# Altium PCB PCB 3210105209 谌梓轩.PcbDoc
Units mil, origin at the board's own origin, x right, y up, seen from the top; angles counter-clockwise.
Board outline 3937.01 x 1968.5 mil, 2 copper layers (Top Layer, Bottom Layer); 93 components, 82 nets, 314 pads, 119 vias.
Unrouted connection lines stored in the file: 3.
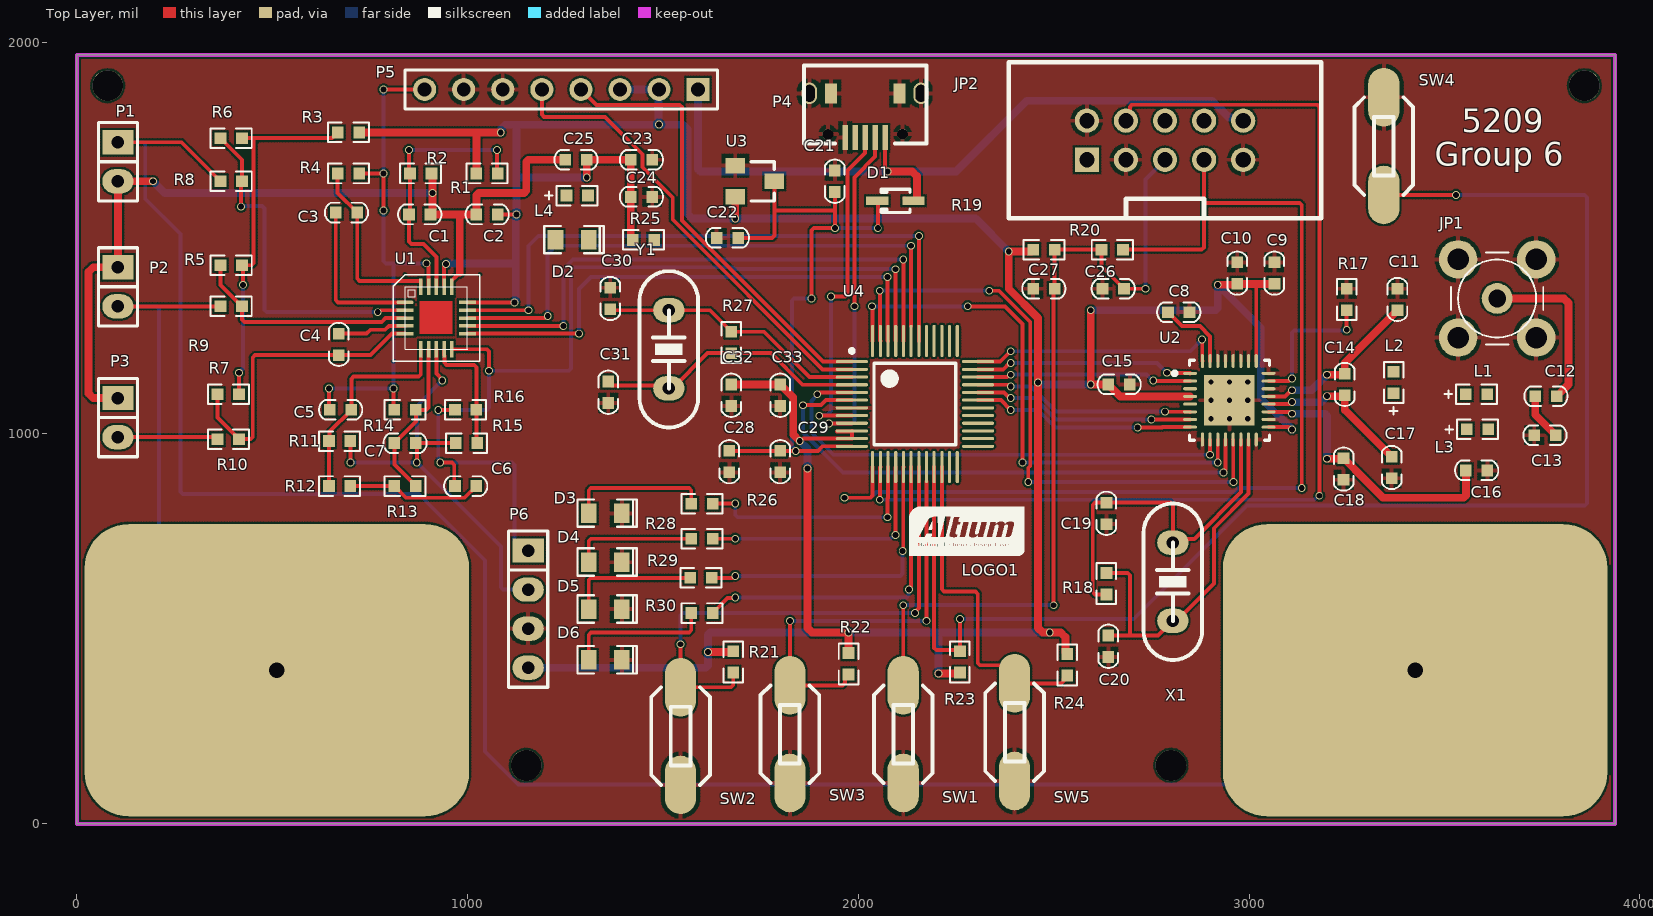
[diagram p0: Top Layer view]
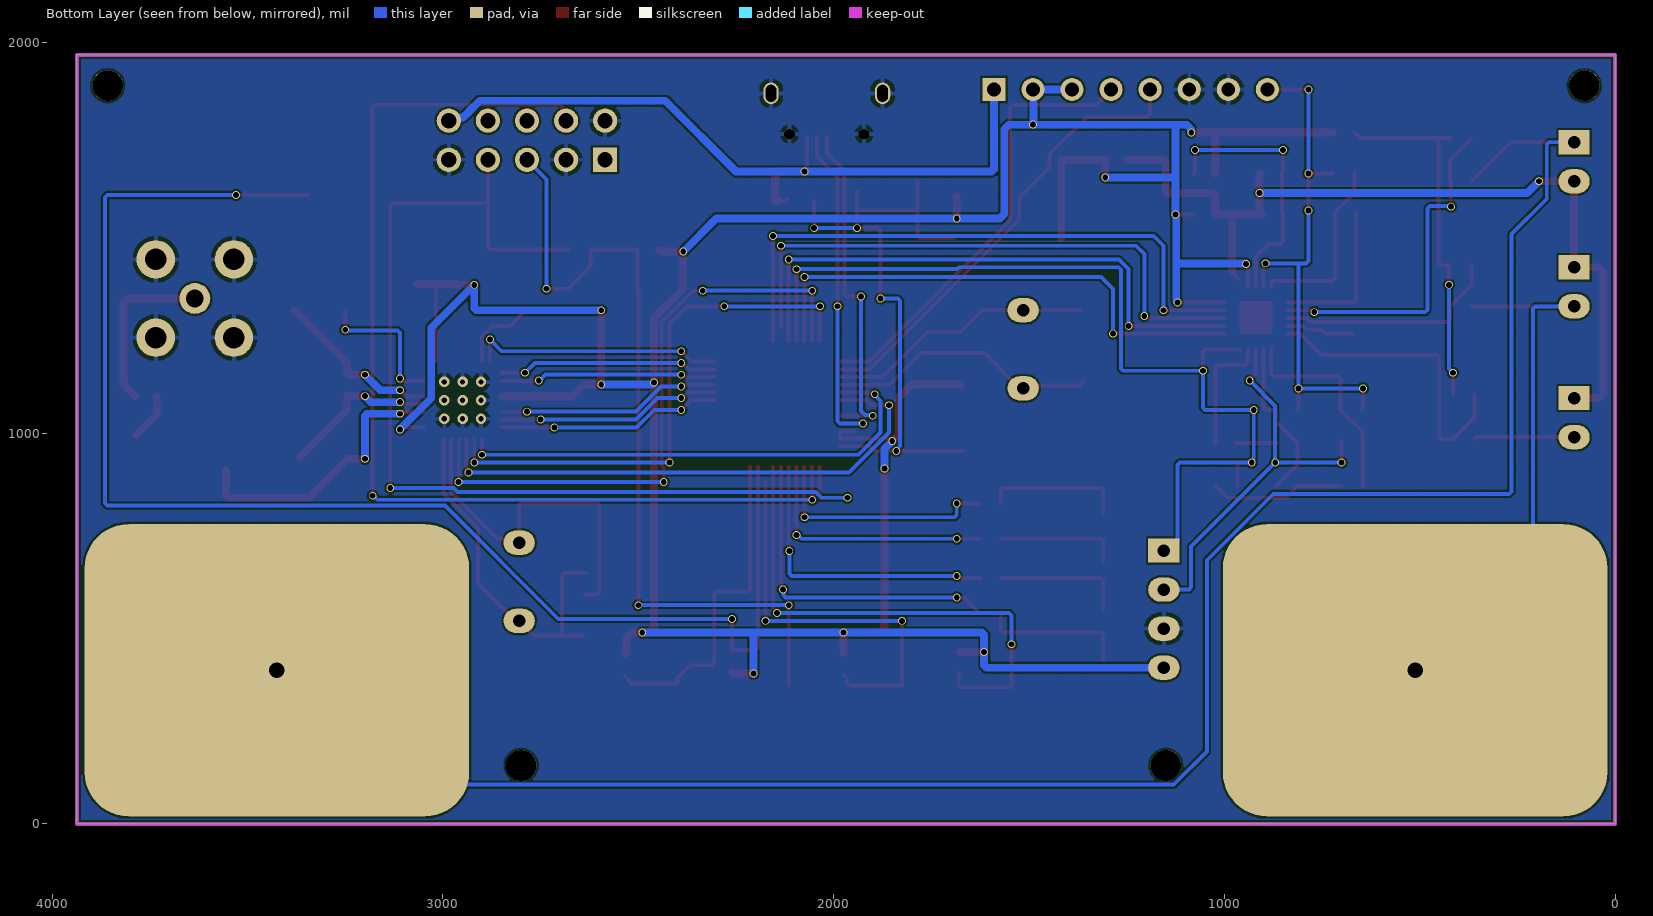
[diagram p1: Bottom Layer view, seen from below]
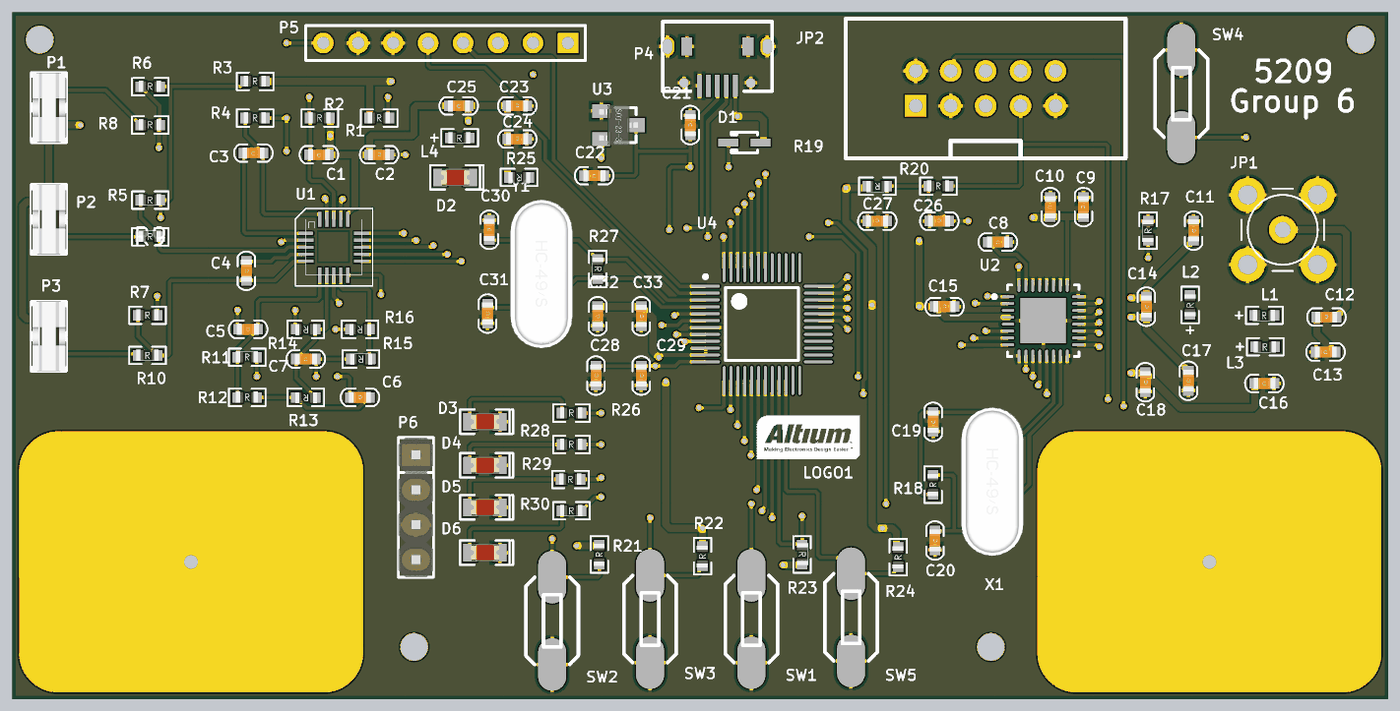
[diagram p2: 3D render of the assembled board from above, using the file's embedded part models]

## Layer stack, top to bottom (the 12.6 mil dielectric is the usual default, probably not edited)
Top Solder: solder mask 0.4, Solder Resist, Dk 3.5
Top Layer: signal copper 1.4
Dielectric 1: dielectric 12.6, FR-4, Dk 4.8
Bottom Layer: signal copper 1.4
Bottom Solder: solder mask 0.4, Solder Resist, Dk 3.5

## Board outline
0,0 0,1968.5 3937.01,1968.5 3937.01,0

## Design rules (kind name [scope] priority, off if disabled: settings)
Clearance [All] p1: gap=5 ignorepadtopadclearanceinfootprint=FALSE
PolygonConnect [All] p1: connectstyle=Relief reliefconductorwidth=10 reliefentries=4 polygonreliefangle="90 Angle" airgapwidth=10
RoutingVias [All] p1: holewidth=28 width=50 viastyle="Through Hole" minholewidth=28 minwidth=50 maxholewidth=28 maxwidth=50
SolderMaskExpansion [All] p1: expansion=4 istentingtop=FALSE
Width [All] p1: maxlimit=25 minlimit=10 preferedwidth=10
30 further rules are at their usual default settings.

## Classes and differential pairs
component class "Part3 3210105209 谌梓轩": C8 C9 C10 C11 C12 C13 C14 C15 C16 C17 C18 C19 C20 JP1 L1 L2 L3 R17 R18 U2 X1
component class "Part2 3210105209 谌梓轩": C21 C22 C23 C24 C25 C26 C27 C28 C29 C30 C31 C32 C33 D1 D2 D3 D4 D5 D6 JP2 L4 P4 P5 P6 R19 R20 R21 R22 R23 R24 R25 R26 R27 R28 R29 R30 SW1 SW2 SW3 SW4 SW5 U3 U4 Y1
component class "Part1 3210105209 谌梓轩": C1 C2 C3 C4 C5 C6 C7 LOGO1 P1 P2 P3 R1 R2 R3 R4 R5 R6 R7 R8 R9 R10 R11 R12 R13 R14 R15 R16 U1

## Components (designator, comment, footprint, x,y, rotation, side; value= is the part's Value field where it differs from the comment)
C1 "0.1uF" 0603C 877.5,1560 r0 top value=75nF
C2 "0.1uF" 0603C 1050,1560 r180 top value=75nF
C3 "0.22uF" 0603C 690,1565 r0 top value=75nF
C4 "1nF" 0603C 670,1227.5 r90 top value=75nF
C5 "0.22uF/NC" 0603C 675,1060 r180 top value=75nF
C6 "3.3nF/NC" 0603C 995,865 r180 top value=75nF
C7 "22nF/NC" 0603C 840,975 r0 top value=75nF
C8 "10nF" 0603C 2820,1310 r0 top value=75nF
C9 "33PF" 0603C 3065,1410 r270 top value=75nF
C10 "4.7nF" 0603C 2970,1410 r270 top value=75nF
C11 "18PF" 0603C 3380,1342.5 r90 top value=75nF
C12 "6.8PF" 0603C 3760,1095 r180 top value=75nF
C13 "NC" 0603C 3757.5,995 r0 top value=75nF
C14 "NC" 0603C 3245,1125 r90 top value=75nF
C15 "33P" 0603C 2667.5,1125 r180 top value=75nF
C16 "180PF" 0603C 3582.5,905 r0 top value=75nF
C17 "18PF" 0603C 3365,912.5 r90 top value=75nF
C18 "33nF" 0603C 3242.07,908.5 r90 top value=75nF
C19 "15P" 0603C 2635,795 r90 top value=75nF
C20 "15P" 0603C 2640,455 r90 top value=75nF
C21 "106" 0603C 1940,1645 r270 top value=75nF
C22 "104" 0603C 1665,1500 r0 top value=75nF
C23 "106" 0603C 1445,1700 r180 top value=75nF
C24 "104" 0603C 1445,1605 r180 top value=75nF
C25 "106" 0603C 1277.5,1700 r0 top value=75nF
C26 "106" 0603C 2652.5,1370 r180 top value=75nF
C27 "104" 0603C 2475,1370 r180 top value=75nF
C28 "104" 0603C 1670,927.5 r90 top value=75nF
C29 "106" 0603C 1800,927.5 r90 top value=75nF
C30 "30pF" 0603C 1365,1345 r270 top value=75nF
C31 "30pF" 0603C 1360,1105 r90 top value=75nF
C32 "104" 0603C 1675,1097.5 r90 top value=75nF
C33 "106" 0603C 1800,1097.5 r90 top value=75nF
D1 "1N5819" SOD-323 2095,1595 r180 top
D2 "LED2" LED0805R 1225,1495 r0 top
D3 "LED0805R" LED0805R 1310,795 r0 top
D4 "LED0805R" LED0805R 1310,670 r0 top
D5 "LED0805R" LED0805R 1310,550 r0 top
D6 "LED0805R" LED0805R 1310,420 r0 top
JP1 "BNC" SMA 3635,1345 r180 top
JP2 "JTAG" IDC10L 2585,1700 r0 top
L1 "39nH" 0603-D 3582.5,1100 r0 top
L2 "12nH" 0603-D 3370,1130 r90 top
L3 "39nH" 0603-D 3585,1010 r0 top
L4 "100MHz600R" 0603-D 1280.45,1608.5 r0 top
LOGO1 "LOGO" LOGO 2285,750 r0 top
P1 "LA" SIP2 105,1745 r270 top
P2 "LA" SIP2 105,1425 r270 top
P3 "LA" SIP2 105,1090 r270 top
P4 "USB-mini" USB-Micro 2017.6,1767.05 r0 top
P5 "Header 8" HDR1X8 1590,1880 r180 top
P6 "Header 4" SIP4 1155,550 r270 top
R1 "10M" 0603R 1050,1665 r0 top value=16K
R2 "10M" 0603R 880,1665 r0 top value=16K
R3 "0/NC" 0603R 695,1770 r0 top value=16K
R4 "10M" 0603R 695,1665 r0 top value=16K
R5 "10M" 0603R 395,1430 r0 top value=16K
R6 "10M" 0603R 395,1755 r0 top value=16K
R7 "NC/0" 0603R 387.5,1100 r0 top value=16K
R8 "180K" 0603R 395,1645 r0 top value=16K
R9 "180K" 0603R 395,1325 r0 top value=16K
R10 "360K/NC" 0603R 387.5,985 r0 top value=16K
R11 "100K/NC" 0603R 672.5,980 r0 top value=16K
R12 "1M/NC" 0603R 672.5,865 r0 top value=16K
R13 "1M/NC" 0603R 840,865 r180 top value=16K
R14 "NC/0" 0603R 840,1060 r180 top value=16K
R15 "100K/NC" 0603R 997.5,975 r180 top value=16K
R16 "1M/0" 0603R 995,1060 r180 top value=16K
R17 "22K" 0603R 3250,1342.5 r90 top value=16K
R18 "10M" 0603R 2635,615 r90 top value=16K
R19 "1K" 0603R 2475,1470 r180 top value=16K
R20 "10K" 0603R 2650,1470 r0 top value=16K
R21 "10K" 0603R 1680,415 r90 top value=16K
R22 "10K" 0603R 1975,410 r90 top value=16K
R23 "10K" 0603R 2260,415 r270 top value=16K
R24 "10K" 0603R 2535,407.5 r90 top value=16K
R25 "10M" 0603R 1450,1495 r180 top value=16K
R26 "3.6K" 0603R 1600,820 r0 top value=16K
R27 "10M" 0603R 1675,1232.5 r270 top value=16K
R28 "3.6K" 0603R 1600,730 r0 top value=16K
R29 "3.6K" 0603R 1597.5,630 r0 top value=16K
R30 "3.6K" 0603R 1600,540 r0 top value=16K
SW1 "SW-PB" SW-BP-SMD 2115,230 r90 top
SW2 "SW-PB" SW-BP-SMD 1545,225 r90 top
SW3 "SW-PB" SW-BP-SMD 1825,230 r90 top
SW4 "SW-PB" SW-BP-SMD 3345,1735 r270 top
SW5 "SW-PB" SW-BP-SMD 2400,235 r90 top
U1 "AD8232" QFN-20 840,1335 r0 top
U2 "NRF905" QFN32_M 2949.61,1084.53 r0 top
U3 "XC6206" SOT-23-123 1735,1645 r90 top
U4 "C8051F340/1/4/5" TQFP48_M 2145,1075 r0 top
X1 "16M" CY2 2805,720 r270 top
Y1 "3.2768MHz" CY2 1515,1315 r270 top

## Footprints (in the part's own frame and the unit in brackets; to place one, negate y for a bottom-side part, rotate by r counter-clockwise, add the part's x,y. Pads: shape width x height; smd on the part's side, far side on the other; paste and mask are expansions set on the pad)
0603-D [mil]
  rect 30x30 smd: A(-27.5,0) K(27.5,0)
  silkscreen extent -82,-25 52,25, body extent -33,-16 30,16, height 21
0603C [mil]
  rect 30x30 smd: 1(-27.5,0) 2(27.5,0)
  silkscreen extent -55,-25 55,25, body extent -31,-16 32,16, height 35
0603R [mil]
  rect 30x30 smd: 1(-27.5,0) 2(27.5,0)
  silkscreen extent -52,-25 52,25, body extent -32,-15 30,17, height 21
CY2 [mil]
  oval 62x80 hole 32: 1(0,0) 2(200,0)
  silkscreen extent -100,-75 300,75, body extent -116,-89 309,88, height 138
HDR1X8 [mm] "Connector; Header; 8 Position"
  rect 1.5x1.5 hole 0.9: 1(0,0)
  round 1.5 hole 0.9: 2(2.54,0) 3(5.08,0) 4(7.62,0) 5(10.16,0) 6(12.7,0) 7(15.24,0) 8(17.78,0)
  silkscreen extent -1.27,-1.27 19.05,1.27
IDC10L [mil]
  rect 62x62 hole 39: 1(0,0)
  round 62 hole 39: 2(0,100) 3(100,0) 4(100,100) 5(200,0) 6(200,100) 7(300,0) 8(300,100) 9(400,0) 10(400,100)
  silkscreen extent -200,-150 600,250
LED0805R [mil]
  rect 40x50 smd: 1(0,0) 2(85,0)
  silkscreen extent -29,-35 123,35, body extent 3,-24 83,25, height 43
LOGO [mil]
  silkscreen extent -154,-62 140,62
QFN32_M [mm] "QFN, 32-Leads, Body 5x5mm, Pitch 0.5mm, IPC Low Density"
  oval 0.9x0.2 smd: 1(-2.55,1.75) 2(-2.55,1.25) 3(-2.55,0.75) 4(-2.55,0.25) 5(-2.55,-0.25) 6(-2.55,-0.75) 7(-2.55,-1.25) 8(-2.55,-1.75) 17(2.55,-1.75) 18(2.55,-1.25) 19(2.55,-0.75) 20(2.55,-0.25) 21(2.55,0.25) 22(2.55,0.75) 23(2.55,1.25) 24(2.55,1.75)
  oval 0.2x0.9 smd: 9(-1.75,-2.55) 10(-1.25,-2.55) 11(-0.75,-2.55) 12(-0.25,-2.55) 13(0.25,-2.55) 14(0.75,-2.55) 15(1.25,-2.55) 16(1.75,-2.55) 25(1.75,2.55) 26(1.25,2.55) 27(0.75,2.55) 28(0.25,2.55) 29(-0.25,2.55) 30(-0.75,2.55) 31(-1.25,2.55) 32(-1.75,2.55)
  rect 3.3x3.3 smd: 33(0,0)
  silkscreen extent -3.67,-2.6 2.6,2.6, body extent -2.58,-2.58 2.58,2.58, height 0.8
QFN-20 [mm]
  oval 1.1x0.23 smd: 1(0,0)
  rect 1.1x0.23 smd: 2(0,-0.508) 3(0,-1.016) 4(0,-1.524) 5(0,-2.032) 11(4.064,-2.032) 12(4.064,-1.524) 13(4.064,-1.016) 14(4.064,-0.508) 15(4.064,0)
  rect 0.23x1.1 smd: 6(1.016,-3.048) 7(1.524,-3.048) 8(2.032,-3.048) 9(2.54,-3.048) 10(3.048,-3.048) 16(3.048,1.016) 17(2.54,1.016) 18(2.032,1.016) 19(1.524,1.016) 20(1.016,1.016)
  Top Layer region: 0.926,0.104 0.926,-2.046 3.076,-2.046 3.076,0.104
  Top Layer lines w0.025: -0.762,-3.841 -0.741,-3.821 ; -0.014,1.792 -0.014,1.812 ; 4.85,1.802 4.861,1.812
  silkscreen extent -0.76,-3.84 4.86,1.81
SIP2 [mil]
  rect 62x80 hole 32: 1(0,0)
  oval 62x80 hole 32: 2(100,0)
  silkscreen extent -50,-50 150,50, body extent -50,-50 150,50, height 646
SIP4 [mil]
  rect 62x80 hole 32: 1(-150,0)
  oval 62x80 hole 32: 2(-50,0) 3(50,0) 4(150,0)
  silkscreen extent -200,-50 200,50, body extent -200,-50 200,50, height 118
SMA [mm] "Connector; RF Coaxial, MCX, Thru-Hole; 5 Position; Right-Angle"
  round 2 hole 1.143: 1(0,0)
  round 2.5 hole 1.397: 2(-2.54,2.54) 2(-2.54,-2.54) 2(2.54,2.54) 2(2.54,-2.54)
  silkscreen extent -3,-3 3,3
SOD-323 [mm] "SOD-323/SC-76; 2 Leads; Body 1.7 x 1.3 mm, (LxW)"
  rect 1.45x0.55 smd: 1(1.175,0) 2(-1.175,0)
  silkscreen extent -0.95,-0.75 0.95,0.75
SOT-23-123 [mil]
  rect 40x50 smd: 1(40,50) 2(-40,50) 3(0,-50)
  silkscreen extent -50,-50 50,10, body extent -57,-55 57,55, height 47
SW-BP-SMD [mil]
  oval 150x80 smd: 1(-125,0) 2(125,0)
  silkscreen extent -125,-75 125,75
TQFP48_M [mm] "48-Pin Thin Quad Flat Pack 0.5 mm Pitch, IPC Low Density"
  oval 2.1x0.2 smd: 1(-4.1,2.75) 2(-4.1,2.25) 3(-4.1,1.75) 4(-4.1,1.25) 5(-4.1,0.75) 6(-4.1,0.25) 7(-4.1,-0.25) 8(-4.1,-0.75) 9(-4.1,-1.25) 10(-4.1,-1.75) 11(-4.1,-2.25) 12(-4.1,-2.75) 25(4.1,-2.75) 26(4.1,-2.25) 27(4.1,-1.75) 28(4.1,-1.25) 29(4.1,-0.75) 30(4.1,-0.25) 31(4.1,0.25) 32(4.1,0.75) 33(4.1,1.25) 34(4.1,1.75) 35(4.1,2.25) 36(4.1,2.75)
  oval 0.2x2.1 smd: 13(-2.75,-4.1) 14(-2.25,-4.1) 15(-1.75,-4.1) 16(-1.25,-4.1) 17(-0.75,-4.1) 18(-0.25,-4.1) 19(0.25,-4.1) 20(0.75,-4.1) 21(1.25,-4.1) 22(1.75,-4.1) 23(2.25,-4.1) 24(2.75,-4.1) 37(2.75,4.1) 38(2.25,4.1) 39(1.75,4.1) 40(1.25,4.1) 41(0.75,4.1) 42(0.25,4.1) 43(-0.25,4.1) 44(-0.75,4.1) 45(-1.25,4.1) 46(-1.75,4.1) 47(-2.25,4.1) 48(-2.75,4.1)
  silkscreen extent -4.22,-2.65 2.65,3.57, body extent -3.5,-3.5 3.5,3.5, height 1.6
USB-Micro [mm]
  oval 1x1.4 hole 0.7 slot 1.1 at 90 deg: 0(-3.625,2.615) 0(3.625,2.615)
  round 0.7 hole 0.7: 0(-2.425,-0.035) 0(2.425,-0.035)
  rect 0.8x1.3 smd: 0(-2.225,2.615) 0(2.225,2.615)
  rect 0.35x1.6 smd: 1(1.3,-0.254) 2(0.65,-0.254) 3(0,-0.254) 4(-0.65,-0.254) 5(-1.3,-0.254)
  silkscreen extent -3.98,-0.64 3.98,4.43

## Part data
C1 C2 C3 C4 C5 C6 C7 C8 C9 C10 C11 C12 C13 C14 C15 C16 C17 C18 C19 C20 C21 C22 C23 C24 C25 C26 C27 C28 C29 C30 C31 C32 C33: library part Cap, "Capacitor"
D1: library part DIODE
D2: "Typical RED, GREEN, YELLOW, AMBER GaAs LED"
D3 D4 D5 D6: library part LED0, "Typical INFRARED GaAs LED"
JP2: library part "Header 5X2", "Header, 5-Pin, Dual row"
L1 L2 L3 L4: library part INDUCTOR
P1 P2 P3: library part "Header 2", "Header, 2-Pin"
P5: "Header, 8-Pin"
P6: "Header, 4-Pin"
R1 R2 R3 R4 R5 R6 R7 R8 R9 R10 R11 R12 R13 R14 R15 R16 R17 R18 R19 R20 R21 R22 R23 R24 R25 R26 R27 R28 R29 R30: library part Res2, "Resistor"
U2: library part Component_1_1
X1 Y1: library part CRYSTAL

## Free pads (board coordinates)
  rrect30% 984.25x748.03 hole 39.37: 6(511.81,393.7) 7(3425.2,393.7)
  round 78.74 hole 78.74: 8(78.74,1889.76) 8(1150,150) 8(2800,150) 9(3858.27,1889.76)

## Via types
v1: diameter 20, hole 15, Top Layer to Bottom Layer, 110 vias
v2: diameter 25.98, hole 12.99, Top Layer to Bottom Layer, 9 vias

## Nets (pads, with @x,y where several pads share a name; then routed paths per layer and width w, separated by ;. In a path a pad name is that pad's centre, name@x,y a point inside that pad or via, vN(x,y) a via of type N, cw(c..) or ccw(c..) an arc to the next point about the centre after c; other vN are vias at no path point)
+3.3V: C2.1 C9.2 C10.2 C15.2 C23.2 C24.2 C25.2 C32.2 C33.2 P5.2 P5.3 P6.4 R1.1 R3.2 R19.2 R21.2 R22.2 R23.2 R24.2 R25.2 U1.15 U1.17 U2.4 U2.17 U2.25 U3.2 U4.10 U4.11 | length 9494.6
  Top Layer w10: U1.17 940,1425.58 945,1430.58 v1(945,1433.28) ; U1.15 v1(1120,1335) ; C2.1 v1(1125,1560) ; R25.2@1417.5,1500 R25.2 ; R21.2@1677.5,440 R21.2 ; v1(1850,980) 1852.71,980 1859.12,986.42 U4.11 U4.10 1982.52,1005.04 1945.12,1005.04 U4.10@1945.08,1005 ; C10.2@2967.5,1380 C10.2 ; 3017.5,1382.5 3018.5,1381.5 U2.25 ; U2.17 3101.66,1015.63 3107.29,1010 v1(3110,1010)
  Top Layer w20: R3.2 1022.66,1770 ; R1.1@1022.66,1665.16 1022.66,1770 ; v1(1085,1770) 1022.66,1770 ; v1(1305,1655) C25.2 C23.2 C24.2 R25.2@1417.5,1500 ; v1(1615,440) R21.2@1677.5,440 ; C32.2 C33.2 1833.28,1091.72 1833.28,996.72 v1(1850,980) ; v1(1685,1550) U3.2 ; v1(1870,910) 1870,501.72 1881.72,490 v1(1975,490) R22.2 ; v1(2205,385) 2257.5,385 R23.2 ; R19.2 2442.5,1465 v1(2385,1465) 2385,1370 2460,1295 v1(2460,1130) 2460,501.72 2471.72,490 2518.28,490 2530,478.28 2530,440 R24.2 ; v1(2595,1315) v1(2595,1125) C15.2 2670.63,1094.37 U2.4 ; v1(2920,1380) C10.2@2967.5,1380 ; C10.2 3017.5,1382.5 C9.2
  Bottom Layer w20: v1@945,1434.75 1123.28,1434.75 ; v1(1085,1770) 1085,1778.03 1096.72,1789.75 1125,1789.75 ; v1@1120,1336.46 1123.28,1339.75 1123.28,1434.75 ; 1125.42,1654.75 v1@1304.75,1654.75 ; P6.4 1609.14,400 1615,405.86 1615,484.14 1620.86,490 v1(1975,490) 2199.14,490 ; P5.3@1390.25,1879.75 P5.2@1489.75,1879.75 ; P5.2 1488.28,1878.28 1488.28,1791.72 v1(1490,1790) 1489.75,1789.75 1125,1789.75 ; v1@1490.25,1789.75 1551.57,1789.75 1563.28,1778.03 1563.28,1561.46 1575,1549.75 v1@1684.75,1549.75 ; v1(1685,1550) 2300,1550 v1(2385,1465) ; v1(1850,980) 1850.36,980 1870,960.36 v1(1870,910) ; v1(2205,385) 2205,484.14 2199.14,490 ; v1(2460,1130) 2465,1125 v1(2595,1125) ; v1(2490,490) 2199.14,490 ; v1(2595,1315) 2914.14,1315 2920,1320.86 v1(2920,1380) 3030,1270 3030,1090 v1(3110,1010) ; 1123.28,1434.75 1123.28,1558.28 v1(1125,1560) 1125,1789.75
+5V: D1.2 JP2.10 P4.1 P5.1 | length 1964.9
  Top Layer w10: P4.1 2068.78,1678.93 2075,1672.71 v1(2075,1670) ; D1.2@2117.72,1600.83 2123.54,1595 D1.2
  Top Layer w20: v1(2075,1670) 2138.28,1670 2150,1658.28 2150,1595.83 2149.17,1595 D1.2
  Bottom Layer w20: P5.1 1590,1675.86 1595.86,1670 v1(2075,1670) 2250,1670 2431,1851 2906.12,1851 2936,1821.12 2936,1820.7 2948.66,1808.04 2976.96,1808.04 JP2.10
AGND: C1.2 C2.2 C25.1 P1.2 P2.1 P3.1 R2.2 U1.16 | length 2325.9
  Top Layer w10: C1.2 970,1560 ; U1.16@960.47,1391.65 970,1401.18 980,1411.18
  Top Layer w20: P3.1 41.72,1090 30,1101.72 30,1413.28 41.72,1425 P2.1 P1.2 v1(195,1645) ; C1.2 915,1560 970,1560 C2.2 1022.5,1609.14 1028.36,1615 1144.14,1615 1150,1620.86 1150,1694.14 1155.86,1700 C25.1 ; R2.2 910,1662.5 v1(910,1615) C1.2@910,1565 ; 980,1411.18 980,1560
  Bottom Layer w20: v1(195,1645) 225,1615 v1(910,1615)
C2CK: JP2.7 R20.2 U4.13 | length 2737.5
  Top Layer w10: v1(1965,835) 2030.87,835 2036.73,840.86 U4.13 ; R20.2 2879.14,1470 2885,1475.86 2885,1589.67 ; JP2.7 2885,1589.67 ; v1(3135,860) 3135,1583.81 3129.14,1589.67 2885,1589.67
  Bottom Layer w10: v1(1965,835) 2031.72,835 2046.72,850 2963.28,850 2973.28,860 v1(3135,860)
C2D: JP2.4 U4.14 | length 2737.6
  Top Layer w10: v1(2055,830) 2055.71,830.71 2055.71,912.87 U4.14 ; JP2.4 2694.91,1809.91 2694.91,1835.14 2700.77,1841 3174.14,1841 3180,1835.14 v1(3180,840)
  Bottom Layer w10: v1(2055,830) 3167.29,830 3177.29,840 v1(3180,840)
D+: P4.3 U4.8 | length 876.2
  Top Layer w10: v1(1900,1045) 1900.24,1045.24 1983.35,1045.24 U4.8 ; v1(1930,1350) 1966.4,1350 1972.26,1355.86 1972.26,1672.26 2017.52,1717.52 2017.52,1756.97 P4.3
  Bottom Layer w10: v1(1900,1045) 1901.91,1046.91 1919.49,1046.91 1930,1057.43 v1(1930,1350)
D-: P4.2 U4.9 | length 875
  Top Layer w10: v1(1924.8,1025) 1925.19,1025.39 1983.19,1025.39 U4.9 ; v1(1990,1325) 1990,1655 2043.19,1708.19 P4.2
  Bottom Layer w10: v1(1924.8,1025) 1984.14,1025 1990,1030.86 v1(1990,1325)
GND: C8.2 C9.1 C10.1 C11.2 C13.1 C15.1 C16.2 C17.1 C18.1 C19.1 C20.1 C21.1 C22.1 C23.1 C24.1 C26.2 C27.2 C28.1 C29.1 C30.1 C31.1 C32.1 C33.1 D3.2 D4.2 D5.2 D6.2 JP1.2 JP2.2 JP2.3 JP2.9 P4.0 P4.5 P5.6 P5.7 P6.3 R17.2 SW1.1 SW2.1 SW3.1 SW4.1 SW5.1 U2.5 U2.9 U2.16 U2.18 U2.22 U2.24 U2.26 U2.27 U2.28 U2.29 U2.30 U2.33 U3.1 U4.7
  other v2: 2902.36,1037.28 2949.61,1037.28 2996.85,1037.28 2902.36,1084.53 2949.61,1084.53 2996.85,1084.53 2902.36,1131.77 2949.61,1131.77 2996.85,1131.77
LA: P1.1 pad.7 R8.1 | length 5181.2
  Top Layer w10: P1.1 267.5,1745 R8.1
  Bottom Layer w10: P1.1 169.14,1745 175,1739.14 175,1600 265,1510 265,850.86 270.86,845 875.07,845 1045,675.07 1045,185.18 1129.55,100.63 3132.13,100.63 pad.7
LA_OUT: C5.2 P5.8 R4.2 R14.2 U1.19 | length 1378.2
  Top Layer w10: v1(645,1115) 645,1062.5 C5.2 ; R4.2 v1(785,1665) v1(785,1570) ; v1(785,1880) P5.8 ; v1(810,1115) 810,1062.5 R14.2 ; v1(895,1435) 895,1432.29 900,1427.29 U1.19
  Bottom Layer w10: v1(645,1115) v1(810,1115) 810,1435 ; v1(785,1570) 785,1440.86 790.86,1435 810,1435 ; v1(785,1665) v1(785,1880) ; v1(895,1435) 810,1435
MISO: U2.10 U4.5 | length 1277.7
  Top Layer w10: v1(1895,1100) 1897.71,1100 1902.23,1104.53 U4.5 ; v1(2900,945) 2900.2,945.2 2900.2,983.94 U2.10
  Bottom Layer w10: v1(1895,1100) 1895,1097.93 1880,1082.93 1880,1001.72 1936.72,945 v1(2900,945)
MOSI: U2.11 U4.48 | length 1407.1
  Top Layer w10: v1(2035,1325) 2035.87,1324.13 2035.87,1237.28 U4.48 ; v1(2280,1325) 2375,1325 2420,1280 v1(2420,925) ; v1(2920,925) v1(2920,925) 2920.04,984.09 U2.11
  Bottom Layer w10: v1(2035,1325) v1(2280,1325) ; v1(2420,925) v1(2920,925)
NetC1_1: C1.1 R1.2 R2.1 U1.18 | length 685.2
  Top Layer w10: v1(850,1725) 850,1667.5 R2.1 852.5,1562.5 C1.1 850,1490.86 855.86,1485 886.72,1485 920,1451.72 U1.18 ; v1(1075,1725) 1075,1667.5 R1.2
  Bottom Layer w10: v1(850,1725) v1(1075,1725)
NetC3_1: C3.1 U1.1 | length 404.1
  Top Layer w10: C3.1 662.5,1340.86 668.36,1335 U1.1
NetC3_2: C3.2 R4.1 U1.20 | length 469.5
  Top Layer w10: R4.1 667.5,1615 C3.2 717.5,1395.89 723.36,1390.03 879.53,1390.03 880,1389.56 U1.20
NetC4_1: C4.1 R7.1 R10.2 U1.5 | length 793.7
  Top Layer w10: R7.1 360,1040 R10.2 444.14,985 450,990.86 450,1194.14 455.86,1200 C4.1 751.92,1200 806.92,1255 U1.5
NetC4_2: C4.2 U1.4 | length 178.3
  Top Layer w10: C4.2 741.67,1255 751.67,1265 788.64,1265 798.64,1275 U1.4
NetC6_1: C6.1 R12.2 R13.2 | length 347.4
  Top Layer w10: R12.2 R13.2 842.5,835 992.5,835 C6.1
NetC8_1: C8.1 U2.31 | length 196.6
  Top Layer w10: C8.1 2828.36,1274.14 2874.14,1274.14 2900.39,1247.89 U2.31
NetC11_1: C11.1 C14.2 U2.21 | length 437.5
  Top Layer w10: U2.21 3091.66,1094.37 3107.29,1110 v1(3110,1110)
  Top Layer w20: v1(3200,1150) 3242.5,1150 C14.2 3245,1180 C11.1
  Bottom Layer w20: v1(3110,1110) 3160,1110 v1(3200,1150)
NetC12_1: C12.1 JP1.1 | length 438.1
  Top Layer w20: JP1.1 3805.81,1345 3817.53,1333.28 3817.53,1125.03 C12.1
NetC12_2: C12.2 C13.2 | length 121.7
  Top Layer w20: C12.2 3732.5,1047.5 C13.2
NetC14_1: C14.1 C17.2 U2.20 | length 411.4
  Top Layer w10: U2.20 3101.98,1074.69 3107.29,1080 v1(3110,1080)
  Top Layer w20: v1(3200,1095) 3242.5,1095 C14.1 3245,1060 C17.2
  Bottom Layer w20: v1@3110.38,1079.62 3184.62,1079.62 v1(3200,1095)
NetC16_1: C16.1 C18.2 U2.19 | length 727.5
  Top Layer w10: U2.19 3102.29,1055 3107.29,1050 v1(3110,1050)
  Top Layer w20: v1(3200,935) 3241.06,935 C18.2 3297.61,880.47 3343.07,835 3549.14,835 3555,840.86 C16.1
  Bottom Layer w20: v1(3110,1050) 3194.14,1050 3200,1044.14 v1(3200,935)
NetC19_2: C19.2 R18.1 U2.14 X1.1 | length 930.5
  Top Layer w10: R18.1 2605.86,587.5 2600,593.36 2600,816.64 2605.86,822.5 2799.14,822.5 2805,816.64 X1.1 2814.95,729.95 2859.95,729.95 2980,850 2980,983.27 U2.14
NetC20_2: C20.2 R18.2 U2.15 X1.2 | length 946.8
  Top Layer w10: R18.2 2689.14,642.5 2695,636.64 2695,482.5 ; C20.2 2695,482.5 ; U2.15 2998.82,845.69 2910,756.87 2910,616 2814,520 X1.2 2767.5,482.5 2695,482.5
NetC26_1: C26.1 C27.1 JP2.5 R19.1 R20.1 SW1.2 | length 2150.6
  Top Layer w10: SW1.2 v1(2115,560) ; v1(2500,560) 2500,1367.5 C27.1 R19.1 R20.1 2622.5,1427.5 C26.1 v1(2735,1370)
  Bottom Layer w10: v1(2115,560) v1(2500,560) ; v1(2735,1370) 2735,1650 JP2.5
NetD2_1: R25.1
NetD3_1: D3.1 R26.1 | length 360.6
  Top Layer w10: D3.1 1310,854.14 1315.86,860 1566.64,860 1572.5,854.14 R26.1
NetD4_1: D4.1 R28.1 | length 319.1
  Top Layer w10: D4.1 1310,724.14 1315.86,730 R28.1
NetD5_1: D5.1 R29.1 | length 336.6
  Top Layer w10: D5.1 1310,624.14 1315.86,630 R29.1
NetD6_1: D6.1 R30.1 | length 375.6
  Top Layer w10: D6.1 1310,484.14 1315.86,490 1566.64,490 1572.5,495.86 R30.1
NetR3_1: R3.1 R5.2 R6.2 R7.2 | length 941.1
  Top Layer w10: R7.2 v1(415,1155) ; R6.2 423.36,1755.86 446.64,1755.86 452.5,1750 452.5,1435.86 446.64,1430 R5.2 425,1427.5 v1(425,1380) ; 446.84,1755.66 653.16,1755.66 R3.1
  Bottom Layer w10: v1(415,1155) 415,1155.86 425,1165.86 v1(425,1380)
NetR5_1: R5.1 R9.2 U1.3 | length 586
  Top Layer w10: R5.1 367.5,1380 R9.2 422.5,1290.86 428.36,1285 780.36,1285 790.36,1295 U1.3
NetR6_1: R6.1 R8.2 U1.2 | length 886.3
  Top Layer w10: R6.1 377.5,1745 422.5,1700 R8.2 420,1642.5 v1(420,1580) ; v1(770,1310) 772.71,1310 777.71,1315 U1.2
  Bottom Layer w10: v1(420,1580) 421.58,1581.58 474.14,1581.58 480,1575.72 480,1315.86 485.86,1310 v1(770,1310)
NetR17_1: R17.1 U2.23 | length 373
  Top Layer w10: U2.23 3101.03,1133.74 3107.29,1140 v1(3110,1140) ; v1(3250,1265) R17.1
  Bottom Layer w10: v1(3110,1140) 3110,1257.23 3115.86,1263.09 3248.09,1263.09 v1(3250,1265)
OPAMP+: C7.1 R13.1 R14.1 U1.7 | length 424.6
  Top Layer w10: R13.1 812.5,920 C7.1 867.5,1030 R14.1 894.14,1060 900,1065.86 U1.7
OPAMP-: R15.1 R16.1 U1.9 | length 316.4
  Top Layer w10: U1.9 940,1198.82 940.47,1198.35 940.47,1180.86 946.33,1175 1016.64,1175 1022.5,1169.14 R16.1 1022.5,977.5 R15.1
P0.7: U2.13 U4.47 | length 1593.7
  Top Layer w10: v1(2055,1365) 2055.71,1364.29 2055.71,1237.13 U4.47 ; v1(2335,1365) 2335.18,1364.82 2360.18,1364.82 2440,1285 2440,916.72 2435,911.72 v1(2435,875) ; U2.13 2959.72,983.86 2959.72,875.28 v1(2960,875)
  Bottom Layer w10: v1(2055,1365) v1(2335,1365) ; v1(2435,875) v1(2960,875)
P1.0: U1.11 U4.46 | length 1366
  Top Layer w10: U1.11 v1(1285,1255) ; v1(2075,1400) 2075,1274.92 2075.04,1274.88 2075.04,1237.48 U4.46
  Bottom Layer w10: v1(1285,1255) 1285,1369.14 1315.86,1400 v1(2075,1400)
P1.1: C6.2 P6.1 R16.2 U1.10 U4.45 | length 2561.3
  Top Layer w10: v1(925,1060) R16.2 ; v1(930,925) 960,925 965.86,919.14 965.86,866.64 C6.2 ; U1.10 1049.14,1215 1055,1209.14 v1(1055,1160) ; v1(2095,1420) 2095.39,1419.61 2095.39,1236.81 U4.45
  Bottom Layer w10: P6.1 1146,700 1120,726 1120,919.14 1114.14,925 v1(930,925) 930,927.71 925,932.71 v1(925,1060) 1049.14,1060 1055,1065.86 v1(1055,1160) 1259.14,1160 1265,1165.86 1265,1419.14 1270.86,1425 1679.08,1425 1684.08,1420 v1(2095,1420)
P1.2: U1.12 U4.44 | length 1479.3
  Top Layer w10: U1.12 v1(1245,1275) ; v1(2115,1445) 2115.24,1444.76 2115.24,1236.65 U4.44
  Bottom Layer w10: v1(1245,1275) 1245,1420.36 1269.64,1445 v1(2115,1445)
P1.3: U1.13 U4.43 | length 1512.2
  Top Layer w10: U1.13 1197.29,1295 1202.29,1300 v1(1205,1300) ; v1(2135,1480) 2135.16,1479.84 U4.43@2135.16,1272.76
  Bottom Layer w10: v1(1205,1300) 1205,1459.14 1225.86,1480 v1(2135,1480)
P1.4: U1.14 U4.42 | length 1599
  Top Layer w10: U1.14 v1(1155.87,1315) ; U4.42 2155,1236.57 v1(2155,1505)
  Bottom Layer w10: v1(1155.87,1315) 1155.87,1480.01 1180.86,1505 v1(2155,1505)
P1.5: U4.41
P1.6: U4.40
P1.7: U4.39
P2.0: U4.38
P2.1: U4.37
P2.2: U2.32 U4.36 | length 652.5
  Top Layer w10: U4.36 2363.27,1183.27 v1(2390,1210) ; v1(2880,1240) 2880.35,1239.65 2880.35,1185.28 U2.32
  Bottom Layer w10: v1(2390,1210) 2850,1210 v1(2880,1240)
P2.3: U2.1 U4.35 | length 560.6
  Top Layer w10: U4.35 2371.06,1163.58 2387.48,1180 v1(2390,1180) ; v1(2790,1155) 2815.3,1155 2816.5,1153.81 2848.83,1153.81 U2.1
  Bottom Layer w10: v1(2390,1180) 2765,1180 v1(2790,1155)
P2.4: U2.2 U4.34 | length 552.1
  Top Layer w10: U4.34 2381.19,1143.9 2387.29,1150 v1(2390,1150) ; v1(2755,1135) 2756.26,1133.74 U2.2
  Bottom Layer w10: v1(2390,1150) 2737.29,1150 2752.29,1135 v1(2755,1135)
P2.5: U2.6 U4.33 | length 571.5
  Top Layer w10: U4.33 2383.08,1124.21 2387.29,1120 v1(2390,1120) ; v1(2785,1055.32) 2785.16,1055.16 2849.06,1055.16 U2.6
  Bottom Layer w10: v1(2390,1120) 2441.72,1120 2506.4,1055.32 v1(2785,1055.32)
P2.6: U2.7 U4.32 | length 571.7
  Top Layer w10: U4.32 2372.77,1104.53 2387.29,1090 v1(2390,1090) ; v1(2750,1035) 2750.16,1035.16 2849.06,1035.16 U2.7
  Bottom Layer w10: v1(2390,1090) 2450.5,1090 2505.5,1035 v1(2750,1035)
P2.7: U2.8 U4.31 | length 572
  Top Layer w10: U4.31 2365.16,1084.84 v1(2390,1060) ; v1(2715,1015) 2777.74,1015 2778.37,1015.63 U2.8
  Bottom Layer w10: v1(2390,1060) 2459.29,1060 2504.29,1015 v1(2715,1015)
P3.0: U4.30
P3.1: U4.29
P3.2: U4.28
P3.3: U4.27
P3.4: U4.26
P3.5: U4.25
P3.6: U4.24
P3.7: U4.23
P4.0: R24.1 SW5.2 U4.22 | length 856.2
  Top Layer w10: U4.22 2213.9,600.86 2219.76,595 2299.78,595 2305.64,589.14 2305.64,412.25 2311.5,406.39 2367.66,406.39 2400,374.06 SW5.2 2519.14,360 2525,365.86 2525,370 R24.1
P4.1: R23.1 SW4.2 U4.21 | length 3647.7
  Top Layer w10: U4.21 2194.21,450.86 2200.07,445 2257.5,445 R23.1 v1(2260,525) ; SW4.2 v1(3530,1610)
  Bottom Layer w10: v1(2260,525) 2705,525 2995,815 3859.14,815 3865,820.86 3865,1604.14 3859.14,1610 v1(3530,1610)
P4.2: R22.1 SW3.2 U4.20 | length 1040
  Top Layer w10: v1(1825,520) SW3.2 1959.57,355 1965.43,360.86 1965.43,372.93 R22.1 ; v1(2174.21,520) 2174.37,520.16 U4.20@2174.37,877.24
  Bottom Layer w10: v1(1825,520) v1(2174.21,520)
P4.3: R21.1 SW2.2 U4.19 | length 1333.4
  Top Layer w10: v1(1545,460) SW2.2 1674.14,350 1680,355.86 R21.1 ; v1(2145,540) 2145,542.71 2154.92,552.63 2154.92,913.5 U4.19
  Bottom Layer w10: v1(1545,460) 1545,534.14 1550.86,540 v1(2145,540)
P4.4: R30.2 U4.18 | length 850.6
  Top Layer w10: R30.2 1665.59,578.09 1683.09,578.09 v1(1685,580) ; v1(2130,600) 2130,602.71 2135.16,607.86 U4.18
  Bottom Layer w10: v1(1685,580) 2122.93,580 2128.79,585.86 2128.79,598.79 v1(2130,600)
P4.5: R29.2 U4.17 | length 766.6
  Top Layer w10: R29.2 1677.29,630 1682.29,635 v1(1685,635) ; v1(2113.57,698.79) 2115,700.22 2115,913.11 U4.17
  Bottom Layer w10: v1(1685,635) 2107.71,635 2113.57,640.86 v1(2113.57,698.79)
P4.6: R28.2 U4.16 | length 645.6
  Top Layer w10: R28.2 v1(1685,730) ; v1(2095,740) 2095.39,740.39 2095.39,913.19 U4.16
  Bottom Layer w10: v1(1685,730) 2082.29,730 2092.29,740 v1(2095,740)
P4.7: R26.2 U4.15 | length 608.1
  Top Layer w10: R26.2 v1(1685,820) ; v1(2075,785) 2075,833.41 2076.1,834.51 U4.15
  Bottom Layer w10: v1(1685,820) 1685,790.86 1690.86,785 v1(2075,785)
RA: P2.2 pad.6 R9.1 | length 1420.4
  Top Layer w10: P2.2 R9.1
  Bottom Layer w10: P2.2 204.14,1325 210,1319.14 210,695.51 pad.6
RL: P3.2 R10.1 | length 257.1
  Top Layer w10: P3.2 355,990 R10.1
RX0: P5.4 U4.1 | length 1151.5
  Top Layer w10: P5.4@1290.43,1879.57 1317.46,1852.54 1329.53,1840.47 1542.95,1840.47 1548.81,1834.61 1548.81,1544.55 1910.09,1183.27 U4.1
SCK: U2.12 U4.6 | length 1405.6
  Top Layer w10: v1(1858.36,1071.91) 1904.62,1071.91 1917.55,1084.84 U4.6 ; v1(2935,900) 2935,902.71 2940,907.71 2940,943.95 2939.76,944.18 U2.12
  Bottom Layer w10: v1(1858.36,1071.91) 1858.36,1002.14 1960.5,900 v1(2935,900)
SW: C5.1 R11.1 R12.1 U1.6 | length 544.5
  Top Layer w10: R12.1 R11.1 646.64,981.64 646.64,1004.14 C5.1 702.5,1139.14 708.36,1145 874.14,1145 880,1150.86 U1.6
TX0: P5.5 U4.2 | length 1180.3
  Top Layer w10: P5.5 1190,1815.86 1195.86,1810 1351.64,1810 1447.5,1714.14 1447.5,1680.86 1525,1603.36 1525,1547.14 1908.56,1163.58 U4.2
UPCLK: U2.3
VBUS: C21.2 C22.2 C28.2 C29.2 D1.1 U3.3 U4.12 | length 1657.8
  Top Layer w10: C28.2 1896.65,955 1908.38,966.73 U4.12 ; C22.2 1779.14,1500 1785,1505.86 1785,1570 ; U3.3 1785,1570 ; v1(1880,1345) 1880,1519.14 1885.86,1525 v1(1940,1525) 1940,1570 ; C21.2 1940,1570 ; D1.1 2050,1593.74 v1(2050,1525) ; 1785,1570 1940,1570
  Bottom Layer w10: v1(1840,955) 1840,957.71 1835,962.71 1835,962.92 1830,967.92 1830,1339.14 1835.86,1345 v1(1880,1345) ; v1(1940,1525) v1(2050,1525)
VREFOUT: C7.2 P6.2 R11.2 R15.2 U1.8 | length 1182.3
  Top Layer w10: v1(700,925) R11.2 ; v1(870,925) 870,972.5 C7.2 R15.2 ; U1.8 920,1152.71 935,1137.71 v1(935,1135)
  Bottom Layer w10: v1(700,925) v1(870,925) ; v1(935,1135) 870,1070 v1(870,925) ; P6.2 1090.86,600 1085,605.86 1085,710 v1(870,925)
XTAL1: C31.2 R27.2 U4.4 Y1.2 | length 701.6
  Top Layer w10: C31.2 1370,1122.5 1507.5,1122.5 Y1.2 1524,1115 1614,1205 R27.2 1776.26,1205 1857.05,1124.21 U4.4
XTAL2: C30.2 R27.1 U4.3 Y1.1 | length 690.5
  Top Layer w10: C30.2 1367.5,1315 Y1.1 1620,1315 R27.1 1758.6,1260 1874.7,1143.9 U4.3
pads on no net: D2.1 D2.2 JP2.1 JP2.6 JP2.8 L1.A L1.K L2.A L2.K L3.A L3.K L4.A L4.K P4.4

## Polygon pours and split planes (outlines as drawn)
GND on Bottom Layer "GND_L02_P-001" (hatched 90Degree grid 4 track 4, remove dead copper, pour order 0): 0,0 3940,0 3940,1970 3939.27,1970.73 -1.17,1970.73 -1.17,-3.83 0,-5
GND on Top Layer "GND_L02_P-001" (hatched 90Degree grid 4 track 4, remove dead copper, pour order 1): 0,0 3940,0 3940,1970 0,1970

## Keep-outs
Keep-Out Layer:
  the board outline again, w10

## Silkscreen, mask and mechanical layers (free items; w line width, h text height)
Top Overlay:
  text "5209" at 3545,1770 h60
  text "Group 6" at 3475,1684.99 h60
